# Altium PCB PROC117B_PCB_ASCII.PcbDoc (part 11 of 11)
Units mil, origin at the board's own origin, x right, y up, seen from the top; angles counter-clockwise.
Board outline 2480.32 x 3185.25 mil, 8 copper layers (Top Layer, L2_GND1, L3_SIG1, L4_PWR1, L5_PWR2, L6_SIG2, L7_GND2, Bottom Layer), stack 57.4 mil thick; 456 components, 292 nets, 7831 pads, 2905 vias.
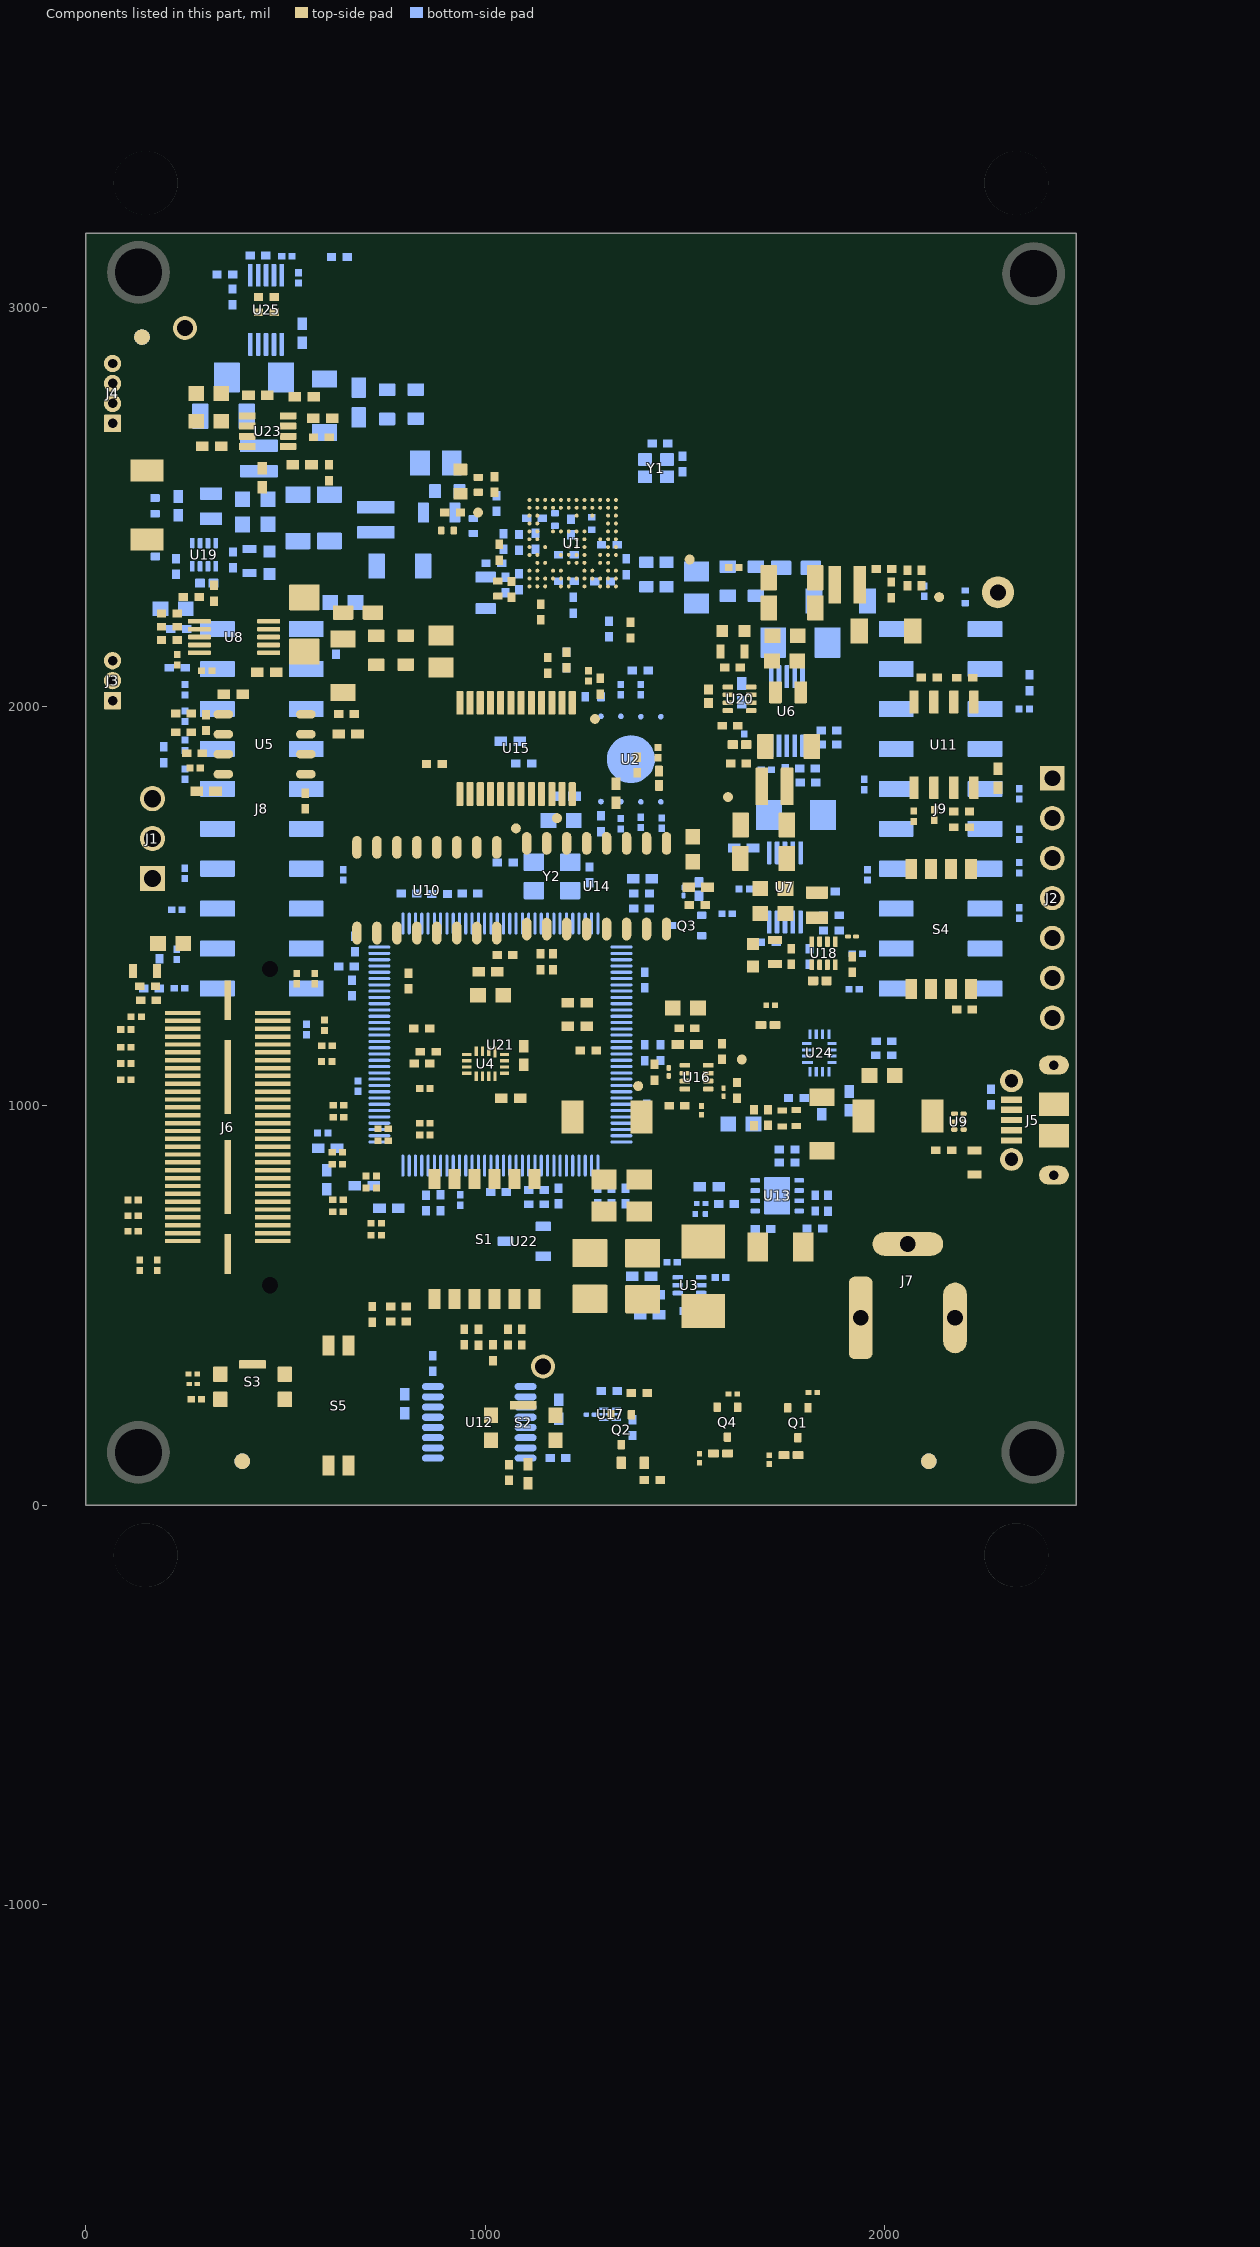
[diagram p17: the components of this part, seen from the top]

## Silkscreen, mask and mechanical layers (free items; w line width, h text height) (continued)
SAMTEC CABLE:
  drawing of 5007 lines, arcs and shapes, not listed
DCA1000:
  drawing of 10999 lines, arcs and shapes, not listed
fanoutbga:
  drawing of 566 lines, arcs and shapes, not listed
PCB_dimesnion_airgap_trace_width:
  lines w0.5: 1112.97,2475.92 1278.32,2475.92 ; 1112.97,2475.92 1112.97,2556.62 ; 1112.97,2475.92 1278.32,2475.92 ; 1112.97,2475.92 1112.97,2517.25 ; 1112.97,2475.92 1278.32,2475.92 ; 1112.97,2475.92 1112.97,2556.62 ; 1112.97,2517.25 1150.36,2517.25 ; 1112.97,2517.25 1150.36,2517.25 ; 1112.97,2517.25 1112.97,2556.62 ; 1112.97,2556.62 1278.32,2556.62 ; 1112.97,2556.62 1278.32,2556.62 ; 1112.97,2556.62 1278.32,2556.62 ; 1112.97,2556.62 1112.97,2476.5 1278.32,2476.5 1278.32,2556.62 ; 1112.97,2556.62 1278.32,2556.62 ; 1150.36,2517.25 ccw(c1150.37,2517.25) 1150.37,2517.25 ; 1150.37,2517.25 ccw(c1150.37,2517.25) 1150.37,2517.25 ; 1150.37,2517.25 ccw(c1150.37,2517.25) 1150.36,2517.25 ; 1150.37,2517.25 1189.73,2517.25 ; 1150.37,2517.25 1189.73,2517.25 ; 1189.73,2517.25 ccw(c1189.74,2517.25) 1189.74,2517.25 ; 1189.74,2517.25 cw(c1189.74,2517.25) 1189.74,2517.25 ; 1189.74,2517.25 ccw(c1189.74,2517.25) 1189.73,2517.25 ; 1189.74,2517.25 1229.1,2517.25 ; 1189.74,2517.25 1229.1,2517.25 ; 1229.1,2517.25 ccw(c1229.11,2517.25) 1229.11,2517.25 ; 1229.11,2517.25 ccw(c1229.11,2517.25) 1229.1,2517.25 ; 1278.32,2475.92 1278.32,2556.62 ; 1278.32,2475.92 1114.96,2475.92 1114.96,2556.62 1140.38,2556.62 1140.38,2536.94 1160.36,2536.94 1160.36,2556.62 1179.75,2556.62 1179.75,2536.94 1199.73,2536.94 1199.73,2556.62 1219.12,2556.62 1219.12,2536.94 1239.1,2536.94 1239.1,2556.62 1278.32,2556.62 ; 1278.32,2475.92 1278.32,2556.62 ; 1278.32,2475.92 1278.32,2556.62 ; 1278.32,2475.92 1278.32,2556.62 ; 1286.2,2349.93 1286.2,2515.28 ; 1286.2,2349.93 1366.9,2349.93 ; 1286.2,2349.93 1366.9,2349.93 ; 1286.2,2349.93 1286.2,2515.28 ; 1286.2,2349.93 1286.2,2515.28 ; 1286.2,2349.93 1366.9,2349.93 ; 1286.2,2349.93 1286.2,2513.29 1366.9,2513.29 1366.9,2487.87 1347.21,2487.87 1347.21,2467.9 1366.9,2467.9 1366.9,2448.5 1347.21,2448.5 1347.21,2428.53 1366.9,2428.53 1366.9,2409.13 1347.21,2409.13 1347.21,2389.16 1366.9,2389.16 1366.9,2349.93 ; 1286.2,2349.93 1366.9,2349.93 ; 1286.2,2515.28 1366.9,2515.28 ; 1286.2,2515.28 1327.53,2515.28 ; 1286.2,2515.28 1366.9,2515.28 ; 1327.53,2399.14 ccw(c1327.53,2399.14) 1327.53,2399.15 ; 1327.53,2399.15 ccw(c1327.53,2399.14) 1327.53,2399.14 ; 1327.53,2399.15 1327.53,2438.51 ; 1327.53,2399.15 1327.53,2438.51 ; 1327.53,2438.51 ccw(c1327.53,2438.51) 1327.53,2438.52 ; 1327.53,2438.51 ccw(c1327.53,2438.51) 1327.53,2438.51 ; 1327.53,2438.52 ccw(c1327.53,2438.51) 1327.53,2438.51 ; 1327.53,2438.52 1327.53,2477.88 ; 1327.53,2438.52 1327.53,2477.88 ; 1327.53,2477.88 ccw(c1327.53,2477.88) 1327.53,2477.89 ; 1327.53,2477.88 ccw(c1327.53,2477.88) 1327.53,2477.88 ; 1327.53,2477.88 cw(c1327.53,2477.88) 1327.53,2477.89 ; 1327.53,2477.89 1327.53,2515.28 ; 1327.53,2477.89 1327.53,2515.28 ; 1327.53,2515.28 1366.9,2515.28 ; 1366.9,2349.93 1366.9,2515.28 ; 1366.9,2349.93 1285.8,2349.93 1285.8,2515.28 1366.9,2515.28 ; 1366.9,2349.93 1366.9,2515.28 ; 1366.9,2349.93 1366.9,2515.28 ; 1366.9,2349.93 1366.9,2515.28 ; 1096.43,2467.42 1294.86,2467.42 1294.86,2564.73 1096.43,2564.73 1096.43,2467.42 ; 1145.72,2518.87 ccw(c1150.36,2517.25) 1155.02,2518.85 1155.02,2556.62 1145.72,2556.62 1145.72,2518.87 ; 1185.09,2518.87 ccw(c1189.73,2517.25) 1194.39,2518.85 1194.39,2556.62 1185.09,2556.62 1185.09,2518.87 ; 1224.46,2518.87 ccw(c1229.1,2517.25) 1233.76,2518.85 1233.76,2556.62 1224.46,2556.62 1224.46,2518.87 ; 1277.69,2333.39 1277.69,2531.82 1375.01,2531.82 1375.01,2333.39 1277.69,2333.39 ; 1329.13,2394.49 cw(c1327.53,2399.15) 1329.15,2403.79 1366.9,2403.79 1366.9,2394.49 1329.13,2394.49 ; 1329.13,2433.87 cw(c1327.53,2438.52) 1329.15,2443.16 1366.9,2443.16 1366.9,2433.86 1329.13,2433.87 ; 1329.13,2473.24 cw(c1327.53,2477.89) 1329.15,2482.53 1366.9,2482.53 1366.9,2473.24 1329.13,2473.24
PROC074B-PCB_dxf:
  drawing of 10310 lines, arcs and shapes, not listed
